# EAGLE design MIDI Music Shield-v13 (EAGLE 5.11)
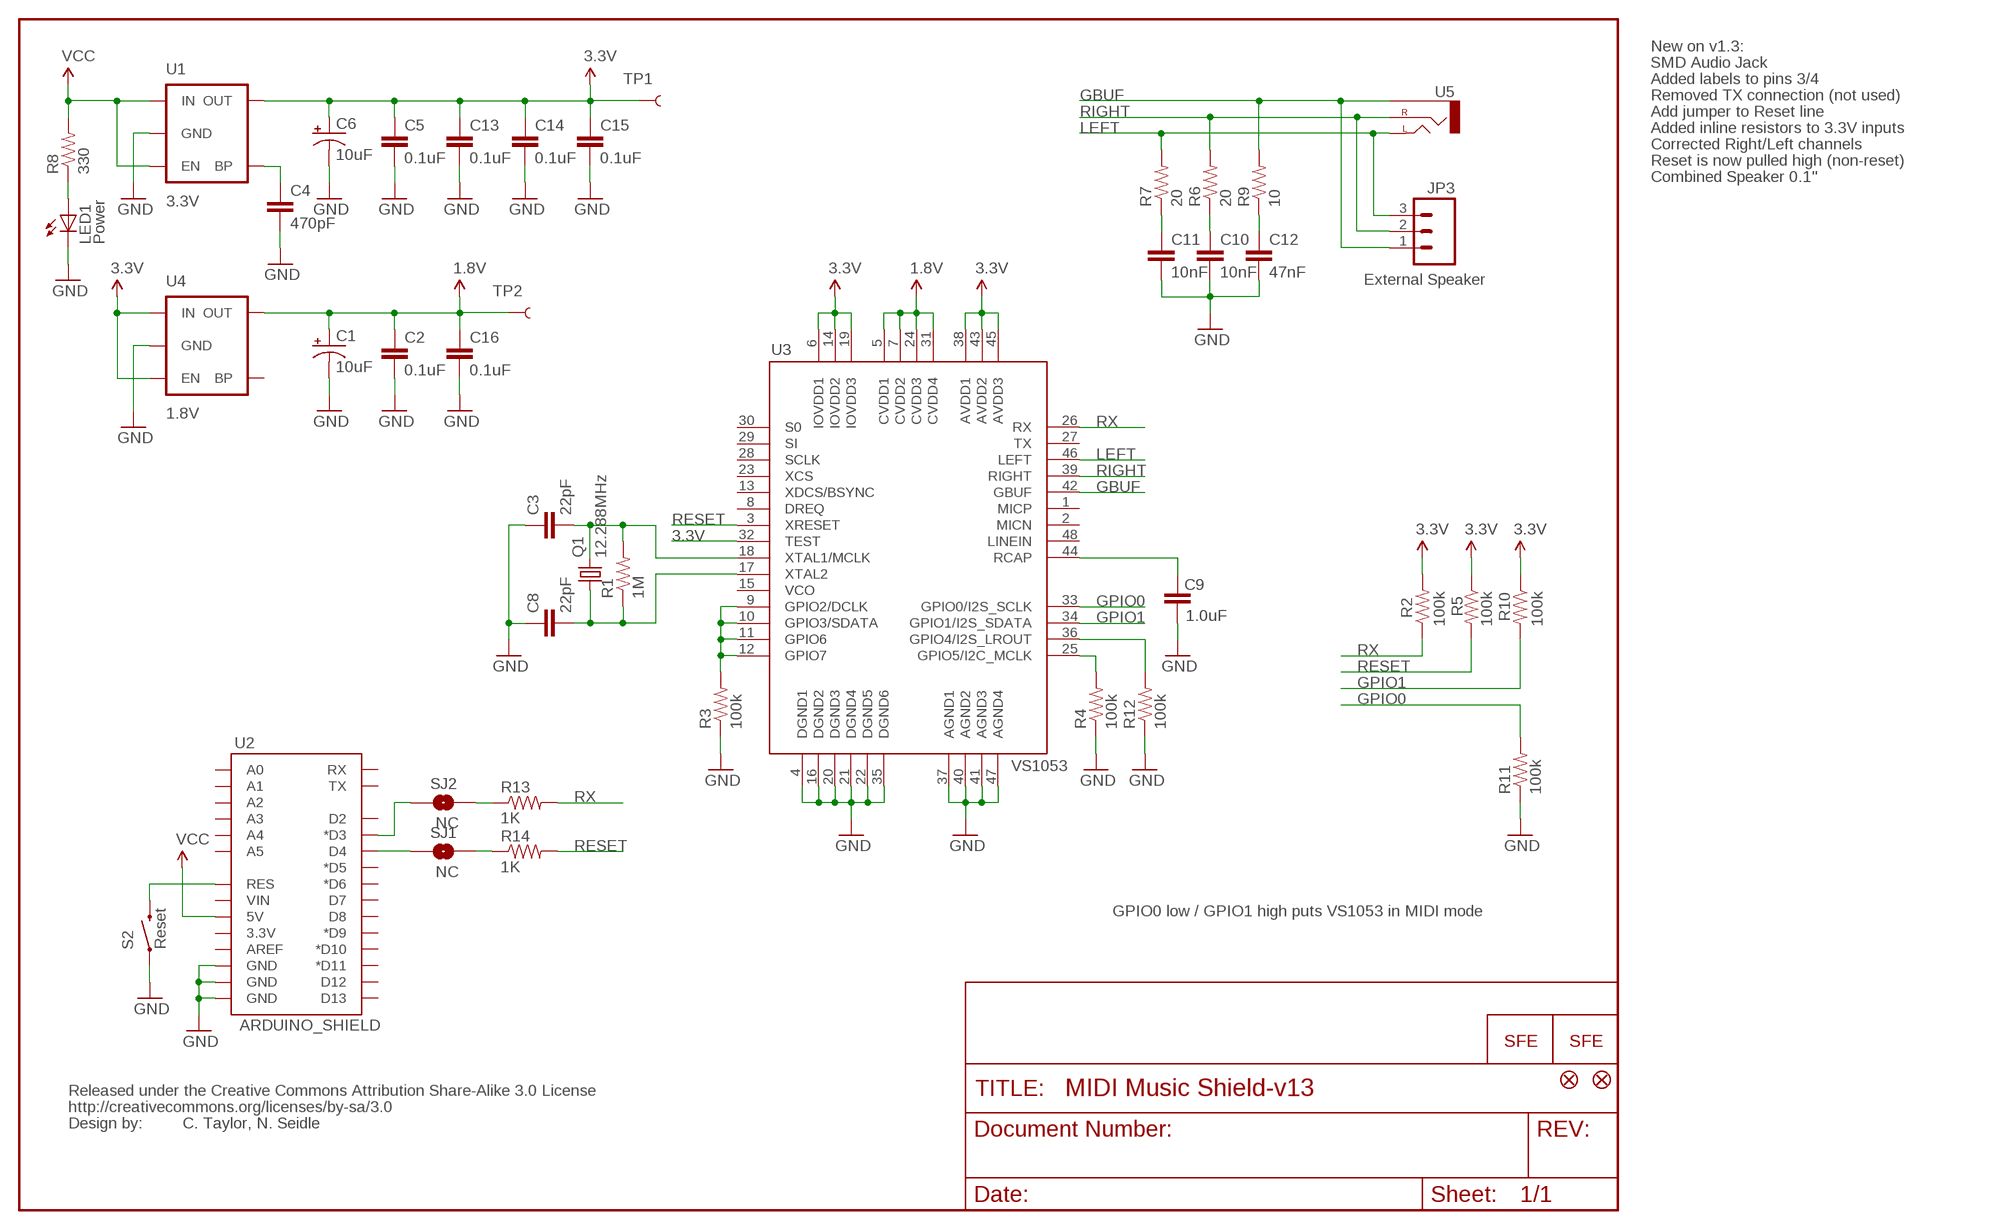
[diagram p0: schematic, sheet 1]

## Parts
C1  10uF  CAP_POL1206  [EIA3216]
C2  0.1uF  CAP0402-CAP  [0402-CAP]
C3  22pF  CAP0402-CAP  [0402-CAP]
C4  470pF  CAP0402-CAP  [0402-CAP]
C5  0.1uF  CAP0402-CAP  [0402-CAP]
C6  10uF  CAP_POL1206  [EIA3216]
C8  22pF  CAP0402-CAP  [0402-CAP]
C9  1.0uF  CAP0402-CAP  [0402-CAP]
C10  10nF  CAP0402-CAP  [0402-CAP]
C11  10nF  CAP0402-CAP  [0402-CAP]
C12  47nF  CAP0402-CAP  [0402-CAP]
C13  0.1uF  CAP0402-CAP  [0402-CAP]
C14  0.1uF  CAP0402-CAP  [0402-CAP]
C15  0.1uF  CAP0402-CAP  [0402-CAP]
C16  0.1uF  CAP0402-CAP  [0402-CAP]
JP3  External Speaker  M03PTH  [1X03]
LED1  Power  LED0603  [LED-0603]
Q1  12.288MHz  CRYSTAL5X3  [CRYSTAL-SMD-5X3]
R1  1M  RESISTOR0402-RES  [0402-RES]
R2  100k  RESISTOR0402-RES  [0402-RES]
R3  100k  RESISTOR0402-RES  [0402-RES]
R4  100k  RESISTOR0402-RES  [0402-RES]
R5  100k  RESISTOR0402-RES  [0402-RES]
R6  20  RESISTOR0402-RES  [0402-RES]
R7  20  RESISTOR0402-RES  [0402-RES]
R8  330  RESISTOR0402-RES  [0402-RES]
R9  10  RESISTOR0402-RES  [0402-RES]
R10  100k  RESISTOR0402-RES  [0402-RES]
R11  100k  RESISTOR0402-RES  [0402-RES]
R12  100k  RESISTOR0402-RES  [0402-RES]
R13  1K  RESISTOR0402-RES  [0402-RES]
R14  1K  RESISTOR0402-RES  [0402-RES]
S2  Reset  SWITCH-MOMENTARY-2SMD  [TACTILE_SWITCH_SMD]
SJ1  NC  SOLDERJUMPERTRACE  [SJ_2S-TRACE]
SJ2  NC  SOLDERJUMPERTRACE  [SJ_2S-TRACE]
TP1  TEST-POINT3X5  [PAD.03X.05]
TP2  TEST-POINT3X5  [PAD.03X.05]
U1  3.3V  V_REG_LDOSMD  [SOT23-5]
U2  ARDUINO_SHIELD  ARDUINO_SHIELDLABEL  [DUEMILANOVE_SHIELD]
U3  VS1053  VS1033  [LQFP-48]
U4  1.8V  V_REG_LDOSMD2  [SC70]
U5  AUDIO-JACKSMD2  [AUDIO-JACK-3.5MM-SMD]
U$3  CREATIVE_COMMONS  [CREATIVE_COMMONS]
U$4  FIDUCIAL1X2  [FIDUCIAL-1X2]
U$5  FIDUCIAL1X2  [FIDUCIAL-1X2]
U$7  LOGO-SFENEW  [SFE-NEW-WEBLOGO]
U$8  LOGO-SFENEW  [SFE-NEW-WEBLOGO]

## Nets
1.8V: C1.A(+) C2.1 C16.1 TP2.P$1 U3.5(CVDD1) U3.7(CVDD2) U3.24(CVDD3) U3.31(CVDD4) U4.5(OUT)
3.3V: C5.1 C6.A(+) C13.1 C14.1 C15.1 R2.2 R5.1 R10.1 TP1.P$1 U1.5(OUT) U3.6(IOVDD1) U3.14(IOVDD2) U3.19(IOVDD3) U3.32(TEST) U3.38(AVDD1) U3.43(AVDD2) U3.45(AVDD3) U4.1(IN) U4.3(EN)
ARST: S2.3 U2.RES
G1: R3.2 U3.9(GPIO2/DCLK) U3.10(GPIO3/SDATA) U3.11(GPIO6) U3.12(GPIO7)
G2: R4.2 U3.25(GPIO5/I2C_MCLK)
GBUF: JP3.1 R9.2 U3.42(GBUF) U5.SLEEVE
GND: C1.C(-) C2.2 C3.1 C4.2 C5.2 C6.C(-) C8.1 C9.1 C10.2 C11.2 C12.2 C13.2 C14.2 C15.2 C16.2 LED1.C R3.1 R4.1 R11.1 R12.1 S2.1 U1.2(GND) U2.GND@0(GND) U2.GND@1(GND) U2.GND@2(GND) U3.4(DGND1) U3.16(DGND2) U3.20(DGND3) U3.21(DGND4) U3.22(DGND5) U3.35(DGND6) U3.37(AGND1) U3.40(AGND2) U3.41(AGND3) U3.47(AGND4) U4.2(GND)
GPIO0: R11.2 U3.33(GPIO0/I2S_SCLK)
GPIO1: R10.2 U3.34(GPIO1/I2S_SDATA)
LEFT: JP3.3 R7.2 U3.46(LEFT) U5.TIP(LEFT)
N$1: C9.2 U3.44(RCAP)
N$2: C12.1 R9.1
N$3: C10.1 R6.1
N$5: C11.1 R7.1
N$6: LED1.A R8.1
N$7: SJ1.1 U2.D4
N$8: R13.1 SJ2.2
N$9: C3.2 Q1.3 R1.2 U3.18(XTAL1/MCLK)
N$10: C8.2 Q1.1 R1.1 U3.17(XTAL2)
N$11: R14.1 SJ1.2
N$13: SJ2.1 U2.D3(*D3)
N$70: C4.1 U1.4(BP)
N$73: R12.2 U3.36(GPIO4/I2S_LROUT)
RESET: R5.2 R14.2 U3.3(XRESET)
RIGHT: JP3.2 R6.2 U3.39(RIGHT) U5.RING(RIGHT)
RX: R2.1 R13.2 U3.26(RX)
VCC: R8.2 U1.1(IN) U1.3(EN) U2.5V
Unconnected: U2.3.3V U2.A0 U2.A1 U2.A2 U2.A3 U2.A4 U2.A5 U2.AREF U2.D2 U2.D5(*D5) U2.D6(*D6) U2.D7 U2.D8 U2.D9(*D9) U2.D10(*D10) U2.D11(*D11) U2.D12 U2.D13 U2.RX U2.TX U2.VIN U3.1(MICP) U3.2(MICN) U3.8(DREQ) U3.13(XDCS/BSYNC) U3.15(VCO) U3.23(XCS) U3.27(TX) U3.28(SCLK) U3.29(SI) U3.30(S0) U3.48(LINEIN) U4.4(BP)

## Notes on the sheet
- New on v1.3:
- SMD Audio Jack
- Added labels to pins 3/4
- Removed TX connection (not used)
- Add jumper to Reset line
- Added inline resistors to 3.3V inputs
- Corrected Right/Left channels
- Reset is now pulled high (non-reset)
- Combined Speaker 0.1"
- GPIO0 low / GPIO1 high puts VS1053 in MIDI mode
- C. Taylor, N. Seidle

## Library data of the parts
C1 C6 = SparkFun:CAP_POL: Capacitor Polarized
C2-C5 C8-C16 = SparkFun:CAP: Capacitor
JP3 = SparkFun:M03: Header 3 Standard 3-pin 0.1" header. Use with straight break away headers (SKU : PRT-00116), right angle break away headers (PRT-00553), swiss pins (PRT-00743), machine pins (PRT-00117), and female headers (PRT-00115). Molex polarized connector foot print use with SKU : PRT-08232 with associated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
LED1 = SparkFun:LED: LEDs
Q1 = SparkFun:CRYSTAL: Crystals
R1-R14 = SparkFun:RESISTOR: Resistor
S2 = SparkFun:SWITCH-MOMENTARY-2
SJ1 SJ2 = SparkFun:SOLDERJUMPER: Solder Jumper
TP1 TP2 = SparkFun:TEST-POINT
U1 U4 = SparkFun:V_REG_LDO: Voltage Regulator LDO Standard 150mA LDO voltage regulator in SOT-23 layout. Micrel part MIC5205. BP (by-pass) pin is used to lower output noise with 470pF cap.
U2 = SparkFun:ARDUINO_SHIELD
U3 = SparkFun:VS1033
U5 = SparkFun:AUDIO-JACK: 3.5mm Audio Jack Simple 3.5mm common PCB mount audio jack. SKU: PRT-08032
U$3 = SparkFun:CREATIVE_COMMONS
U$4 U$5 = SparkFun:FIDUCIAL: Fiducial Alignment Points
U$7 U$8 = SparkFun:LOGO-SFE: Spark Fun Electronics PCB Logo

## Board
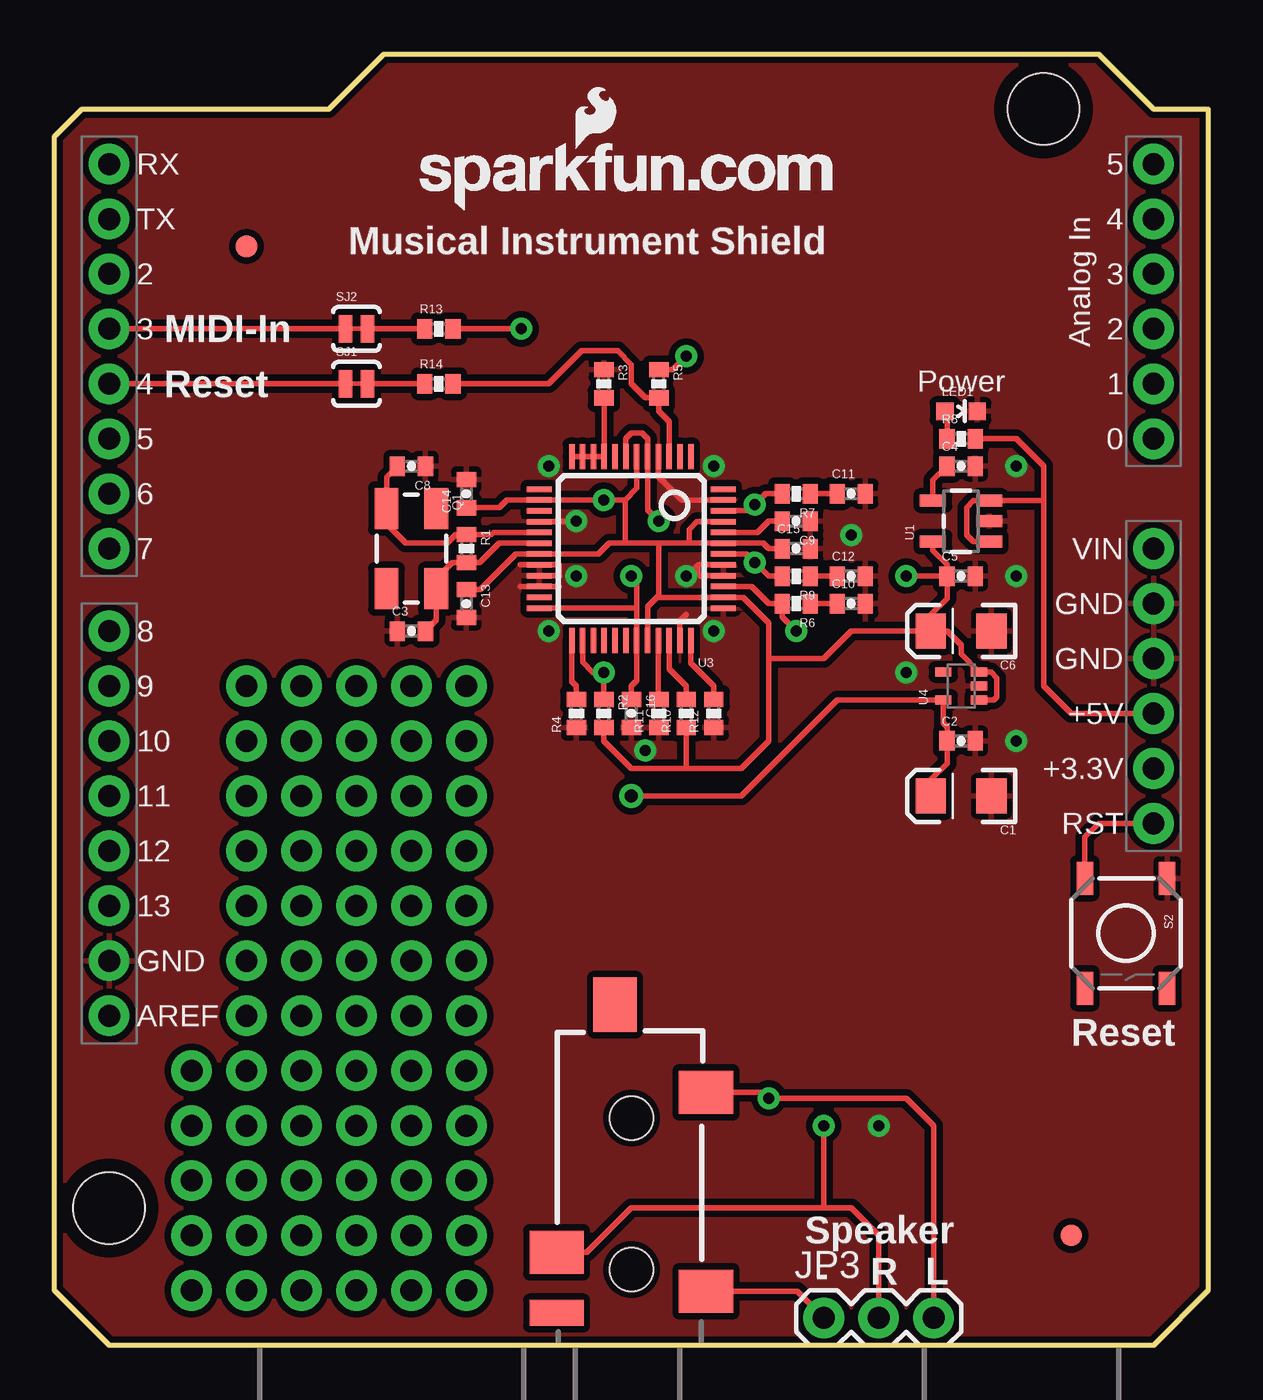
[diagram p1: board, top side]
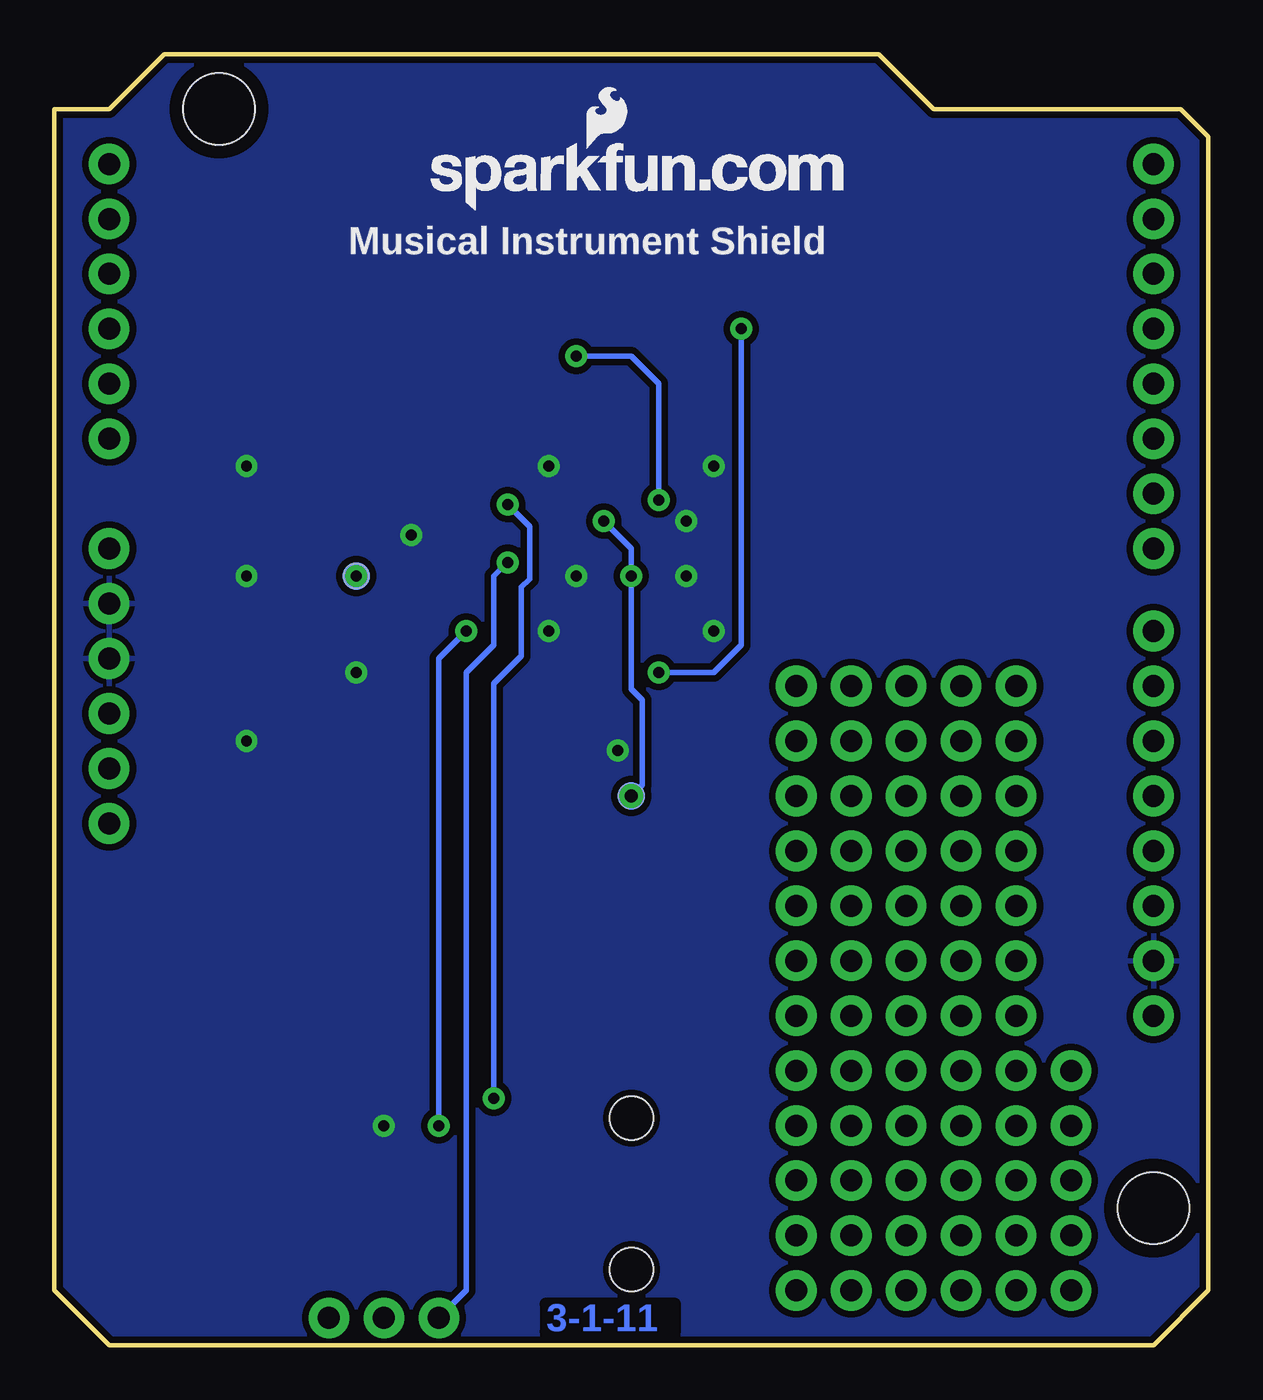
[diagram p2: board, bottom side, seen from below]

Size 53.34 x 59.69 mm. Coordinates in mm from the lower left corner, seen from the top.
Outline: 0,55.88 1.27,57.15 12.7,57.15 15.24,59.69 48.26,59.69 50.8,57.15 53.34,57.15 53.34,2.54 50.8,0 2.54,0 0,2.54 0,55.88
Copper layers (1*16): Top 0.035mm / dielectric 1.5mm / Bottom 0.035mm
Design rules "SparkFun *": minimum track width 8mil, minimum drill 20mil, track to track 8mil, track to pad 8mil, pad to pad 8mil, via to via 8mil, smd to smd 8mil, copper to edge 9mil, drill to drill 7mil, minimum pad ring 12mil, minimum via ring 10mil, stop-mask expansion 4mil, vias tented up to drill 20mil, thermal gap 10mil

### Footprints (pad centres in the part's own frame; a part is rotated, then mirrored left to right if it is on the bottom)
EIA3216 = smd 1.4 x 1.6: A 1.4,0; C -1.4,0
0402-CAP = smd 0.7 x 0.9: 1 -0.65,0; 2 0.65,0
1X03 = drill 1.016 pad 1.88 round: 1 0,0; 2 2.54,0; 3 5.08,0
LED-0603 = smd 0.8 x 0.8: A 0,-0.75; C 0,0.75
CRYSTAL-SMD-5X3 = smd 1.9 x 1.1: 1 -1.85,-1.15; 2 1.85,-1.15; 3 1.85,1.15; 4 -1.85,1.15
0402-RES = smd 0.7 x 0.9: 1 -0.65,0; 2 0.65,0
TACTILE_SWITCH_SMD = smd 1.524 x 0.762: 1 -2.54,1.905; 2 2.54,1.905; 3 -2.54,-1.905; 4 2.54,-1.905
SJ_2S-TRACE = smd 0.635 x 1.27: 1 -0.508,0; 2 0.508,0
PAD.03X.05 = smd 1.27 x 1.27: P$1 0,0
SOT23-5 = smd 0.55 x 1.2: 1 -0.95,-1.3; 2 0,-1.3; 3 0.95,-1.3; 4 0.95,1.3; 5 -0.95,1.3
DUEMILANOVE_SHIELD = drill 1.016 pad 1.88 round: 3.3V 50.8,26.67; 5V 50.8,29.21; A0 50.8,41.91; A1 50.8,44.45; A2 50.8,46.99; A3 50.8,49.53; A4 50.8,52.07; A5 50.8,54.61; AREF 2.54,15.24; D2 2.54,49.53; D3 2.54,46.99; D4 2.54,44.45; D5 2.54,41.91; D6 2.54,39.37; D7 2.54,36.83; D8 2.54,33.02; D9 2.54,30.48; D10 2.54,27.94; D11 2.54,25.4; D12 2.54,22.86; D13 2.54,20.32; GND@0 50.8,31.75; GND@1 50.8,34.29; GND@2 2.54,17.78; RES 50.8,24.13; RX 2.54,54.61; TX 2.54,52.07; VIN 50.8,36.83 | hole 3.302: 45.72,57.15; 2.54,6.35
LQFP-48 = smd 0.254 x 1.143: 1 -2.75,-4.25; 2 -2.25,-4.25; 3 -1.75,-4.25; 4 -1.25,-4.25; 5 -0.75,-4.25; 6 -0.25,-4.25; 7 0.25,-4.25; 8 0.75,-4.25; 9 1.25,-4.25; 10 1.75,-4.25; 11 2.25,-4.25; 12 2.75,-4.25; 25 2.75,4.25; 26 2.25,4.25; 27 1.75,4.25; 28 1.25,4.25; 29 0.75,4.25; 30 0.25,4.25; 31 -0.25,4.25; 32 -0.75,4.25; 33 -1.25,4.25; 34 -1.75,4.25; 35 -2.25,4.25; 36 -2.75,4.25 | smd 1.143 x 0.254: 13 4.25,-2.75; 14 4.25,-2.25; 15 4.25,-1.75; 16 4.25,-1.25; 17 4.25,-0.75; 18 4.25,-0.25; 19 4.25,0.25; 20 4.25,0.75; 21 4.25,1.25; 22 4.25,1.75; 23 4.25,2.25; 24 4.25,2.75; 37 -4.25,2.75; 38 -4.25,2.25; 39 -4.25,1.75; 40 -4.25,1.25; 41 -4.25,0.75; 42 -4.25,0.25; 43 -4.25,-0.25; 44 -4.25,-0.75; 45 -4.25,-1.25; 46 -4.25,-1.75; 47 -4.25,-2.25; 48 -4.25,-2.75
SC70 = smd 0.4 x 0.75: 1 -0.65,-0.825; 2 0,-0.825; 3 0.65,-0.825; 4 0.65,0.825; 5 -0.65,0.825
AUDIO-JACK-3.5MM-SMD = smd 2 x 2.5: RING 4.3,3.45; SLEEVE 2.5,-3.45; TIP 11.7,-3.45 | smd 1.2 x 2.5: RSH 1.5,3.45 | smd 2.5 x 2: TSH 15.75,0.75 | hole 2: 3.5,0; 10.5,0
FIDUCIAL-1X2 = smd 1 x 1: 1 0,0

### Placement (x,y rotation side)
C1  41.91,25.4 180 top
C2  41.91,27.94 0 top
C3  16.51,33.02 0 top
C4  41.91,40.64 0 top
C5  41.91,35.56 0 top
C6  41.91,33.02 180 top
C8  16.51,40.64 180 top
C9  34.29,38.1 180 top
C10  36.83,34.29 0 top
C11  36.83,39.37 0 top
C12  36.83,35.56 0 top
C13  19.05,34.29 270 top
C14  19.05,39.37 90 top
C15  34.29,36.83 0 top
C16  26.67,29.21 270 top
JP3  35.56,1.27 0 top
LED1  41.91,43.18 270 top
Q1  16.51,36.83 270 top
R1  19.05,36.83 270 top
R2  25.4,29.21 270 top
R3  25.4,44.45 270 top
R4  24.13,29.21 90 top
R5  27.94,44.45 270 top
R6  34.29,34.29 180 top
R7  34.29,39.37 180 top
R8  41.91,41.91 0 top
R9  34.29,35.56 180 top
R10  29.21,29.21 90 top
R11  27.94,29.21 90 top
R12  30.48,29.21 90 top
R13  17.78,46.99 0 top
R14  17.78,44.45 0 top
S2  49.53,19.05 270 top
SJ1  13.97,44.45 0 top
SJ2  13.97,46.99 0 top
TP1  39.37,35.56 0 bottom
TP2  26.67,25.4 0 bottom
U1  41.91,38.1 90 top
U2  0,0 0 top
U3  26.67,36.83 180 top
U4  41.91,30.48 90 top
U5  26.67,0 90 top
U$3  not placed on the board
U$4  46.99,5.08 0 top
U$5  8.89,50.8 0 top
U$7  16.89,52.45 0 top
U$8  35.94,52.45 0 bottom

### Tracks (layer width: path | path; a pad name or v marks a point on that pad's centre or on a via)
1.8V  (via drill 0.51, 0.6)
  Top 0.254: C1.A 40.51,26.16 41.26,26.91 C2.1 41.26,28.59 41.09,28.77 U4.5 36.18,29.83 31.75,25.4 TP2.P$1 | 26.92,34.04 U3.31 26.92,30.73 26.67,30.48 C16.1 | 26.92,34.04 26.92,35.31 v26.67,35.56 | U3.24 26.88,34.08 26.92,34.04 | v27.94,38.1 27.42,38.62 U3.5 27.42,41.92 27.18,42.16 26.67,42.16 26.42,41.91 U3.7
  Bottom 0.254: v27.94,38.1 26.67,36.83 v26.67,35.56 26.67,30.35 26.16,29.84 26.16,25.91 TP2.P$1
  other vias: 26.67,25.4
3.3V  (via drill 0.51)
  Top 0.254: C5.1 41.26,34.53 40.51,33.78 C6.A | C5.1 41.26,36.08 40.61,36.73 U1.5 40.61,36.8 | 26.42,37.08 25.65,37.08 25.15,36.58 U3.19 21.34,36.58 19.7,34.94 C13.1 | 26.42,37.08 27.94,37.08 | 27.94,37.08 29.34,37.08 | 29.34,37.08 U3.43 32.77,37.08 33.02,36.83 C15.1 | U3.45 29.7,38.08 29.34,37.72 29.34,37.08 | 26.42,37.08 26.38,37.12 26.38,39.08 | C14.1 20.56,38.72 20.92,39.08 U3.14 v25.4,39.08 26.38,39.08 | 27.85,34.58 U3.38 31.84,34.58 33.02,33.4 33.02,31.75 | U3.32 27.42,34.15 27.85,34.58 | 27.94,37.08 27.94,34.67 27.85,34.58 | 29.21,26.67 R10.1 | R2.2 25.4,27.94 26.67,26.67 29.21,26.67 | U3.6 26.92,39.62 26.38,39.08 | C6.A 36.83,33.02 35.56,31.75 33.02,31.75 | 29.21,26.67 31.75,26.67 33.02,27.94 33.02,31.75 | U4.1 43.42,29.83 43.56,29.97 43.56,30.86 43.29,31.13 U4.3 41.91,31.95 41.91,32.38 41.27,33.02 C6.A | C5.1 TP1.P$1 | R5.1 28.59,45.1 v29.21,45.72
  Bottom 0.254: v29.21,45.72 26.67,45.72 25.4,44.45 v25.4,39.08
  other vias: 39.37,35.56
ARST
  Top 0.254: S2.3 47.62,23.5 48.26,24.13 U2.RES
G1
  Top 0.254: U3.12 U3.11 U3.10 U3.9 25.42,43.78 R3.2
G2
  Top 0.254: U3.25 23.92,30.69 24.13,30.48 R4.2
GBUF  (via drill 0.51)
  Top 0.254: R9.2 33.02,35.56 v32.38,36.2 32,36.58 U3.42 | U5.SLEEVE 34.33,2.5 JP3.1
  Bottom 0.254: v32.38,36.2 33.02,35.56 33.02,32.38 34.29,31.11 34.29,2.54 JP3.1
GND  (via drill 0.51)
  Top 0.254: U3.4 27.92,40.15 28.99,39.08 U3.47 | v29.21,35.56 29.73,36.08 29.73,35.67 29.84,35.56 29.86,35.58 U3.40 | U3.35 28.92,33.49 29.21,33.78 | U3.16 24.11,38.08 v24.13,38.1 | v24.13,35.56 24.11,35.58 | 29.86,36.09 U3.41 | U3.21 23.35,35.58 | 23.35,35.58 23.37,35.56 | 21.53,36.09 23.35,36.09 23.35,35.58 | 21.53,35.07 23.35,35.07
  other vias: 30.48,33.02 39.37,31.11 27.3,27.51 30.48,40.64 36.83,37.47 22.86,40.64 44.45,35.56 44.45,27.94 44.45,40.64 38.1,10.16 22.86,33.02
  pour Top (isolate 0.305): 0,59.69 53.34,59.69 53.34,0 0,0
  pour Bottom (isolate 0.305): 0,0 0,59.69 53.34,59.69 53.34,0
GPIO0
  Top 0.254: U3.33 27.92,29.88 R11.2
GPIO1
  Top 0.254: U3.34 28.42,31.27 29.21,30.48 R10.2
LEFT  (via drill 0.51)
  Top 0.254: U3.46 32.1,38.58 v32.38,38.86 32.89,39.37 R7.2 | U5.TIP 32.75,11.7 v33.02,11.43 39.37,11.43 40.64,10.16 JP3.3
  Bottom 0.254: v32.38,38.86 31.37,37.85 31.37,35.43 31.75,35.05 31.75,31.88 33.02,30.61 v33.02,11.43
N$1
  Top 0.254: U3.44 32.5,37.58 33.02,38.1 C9.2
N$2
  Top 0.254: R9.1 C12.1
N$3
  Top 0.254: R6.1 C10.1
N$4  (via drill 1.02 pad 1.88)
  other vias: 19.05,22.86
N$5
  Top 0.254: R7.1 C11.1
N$6
  Top 0.254: R8.1 41.26,43.08 LED1.A
N$7
  Top 0.254: U2.D4 SJ1.1
N$8
  Top 0.254: SJ2.2 R13.1
N$9
  Top 0.254: U3.18 20.57,37.08 19.67,36.18 R1.2 18.4,36.18 17.78,35.56 17.78,35.1 Q1.3 17.66,33.52 C3.2
N$10
  Top 0.254: U3.17 20.31,37.58 20.21,37.48 R1.1 18.56,37.48 18.16,37.08 16.26,37.08 15.24,38.1 15.24,38.56 Q1.1 15.36,40.14 C8.2
N$11
  Top 0.254: SJ1.2 R14.1
N$13
  Top 0.254: U2.D3 SJ2.1
N$16  (via drill 1.02 pad 1.88)
  other vias: 8.89,20.32
N$17  (via drill 1.02 pad 1.88)
  other vias: 11.43,20.32
N$18  (via drill 1.02 pad 1.88)
  other vias: 13.97,20.32
N$19  (via drill 1.02 pad 1.88)
  other vias: 16.51,20.32
N$20  (via drill 1.02 pad 1.88)
  other vias: 19.05,20.32
N$28  (via drill 1.02 pad 1.88)
  other vias: 8.89,17.78
N$29  (via drill 1.02 pad 1.88)
  other vias: 11.43,17.78
N$30  (via drill 1.02 pad 1.88)
  other vias: 13.97,17.78
N$31  (via drill 1.02 pad 1.88)
  other vias: 16.51,17.78
N$32  (via drill 1.02 pad 1.88)
  other vias: 19.05,17.78
N$40  (via drill 1.02 pad 1.88)
  other vias: 8.89,15.24
N$41  (via drill 1.02 pad 1.88)
  other vias: 11.43,15.24
N$42  (via drill 1.02 pad 1.88)
  other vias: 13.97,15.24
N$43  (via drill 1.02 pad 1.88)
  other vias: 16.51,15.24
N$44  (via drill 1.02 pad 1.88)
  other vias: 19.05,15.24
N$52  (via drill 1.02 pad 1.88)
  other vias: 8.89,12.7
N$53  (via drill 1.02 pad 1.88)
  other vias: 11.43,12.7
N$54  (via drill 1.02 pad 1.88)
  other vias: 13.97,12.7
N$55  (via drill 1.02 pad 1.88)
  other vias: 16.51,12.7
N$56  (via drill 1.02 pad 1.88)
  other vias: 19.05,12.7
N$64  (via drill 1.02 pad 1.88)
  other vias: 8.89,10.16
N$65  (via drill 1.02 pad 1.88)
  other vias: 11.43,10.16
N$66  (via drill 1.02 pad 1.88)
  other vias: 13.97,10.16
N$67  (via drill 1.02 pad 1.88)
  other vias: 16.51,10.16
N$68  (via drill 1.02 pad 1.88)
  other vias: 19.05,10.16
N$70
  Top 0.254: U1.4 40.61,39.99 C4.1
N$73
  Top 0.254: U3.36 29.42,31.54 30.48,30.48 R12.2
N$76  (via drill 1.02 pad 1.88)
  other vias: 8.89,7.62
N$77  (via drill 1.02 pad 1.88)
  other vias: 11.43,7.62
N$78  (via drill 1.02 pad 1.88)
  other vias: 13.97,7.62
N$79  (via drill 1.02 pad 1.88)
  other vias: 16.51,7.62
N$80  (via drill 1.02 pad 1.88)
  other vias: 19.05,7.62
N$88  (via drill 1.02 pad 1.88)
  other vias: 8.89,5.08
N$89  (via drill 1.02 pad 1.88)
  other vias: 11.43,5.08
N$90  (via drill 1.02 pad 1.88)
  other vias: 13.97,5.08
N$91  (via drill 1.02 pad 1.88)
  other vias: 16.51,5.08
N$92  (via drill 1.02 pad 1.88)
  other vias: 19.05,5.08
N$95  (via drill 1.02 pad 1.88)
  other vias: 19.05,25.4
N$96  (via drill 1.02 pad 1.88)
  other vias: 16.51,25.4
N$97  (via drill 1.02 pad 1.88)
  other vias: 13.97,25.4
N$99  (via drill 1.02 pad 1.88)
  other vias: 8.89,25.4
N$100  (via drill 1.02 pad 1.88)
  other vias: 8.89,2.54
N$101  (via drill 1.02 pad 1.88)
  other vias: 11.43,2.54
N$102  (via drill 1.02 pad 1.88)
  other vias: 13.97,2.54
N$103  (via drill 1.02 pad 1.88)
  other vias: 16.51,2.54
N$104  (via drill 1.02 pad 1.88)
  other vias: 19.05,2.54
N$105  (via drill 1.02 pad 1.88)
  other vias: 8.89,27.94
N$106  (via drill 1.02 pad 1.88)
  other vias: 11.43,25.4
N$107  (via drill 1.02 pad 1.88)
  other vias: 11.43,27.94
N$110  (via drill 1.02 pad 1.88)
  other vias: 13.97,27.94
N$111  (via drill 1.02 pad 1.88)
  other vias: 16.51,27.94
N$112  (via drill 1.02 pad 1.88)
  other vias: 6.35,12.7
N$113  (via drill 1.02 pad 1.88)
  other vias: 6.35,10.16
N$114  (via drill 1.02 pad 1.88)
  other vias: 6.35,7.62
N$115  (via drill 1.02 pad 1.88)
  other vias: 6.35,5.08
N$116  (via drill 1.02 pad 1.88)
  other vias: 6.35,2.54
N$122  (via drill 1.02 pad 1.88)
  other vias: 19.05,27.94
N$123  (via drill 1.02 pad 1.88)
  other vias: 19.05,30.48
N$124  (via drill 1.02 pad 1.88)
  other vias: 16.51,30.48
N$125  (via drill 1.02 pad 1.88)
  other vias: 13.97,30.48
N$126  (via drill 1.02 pad 1.88)
  other vias: 11.43,30.48
N$127  (via drill 1.02 pad 1.88)
  other vias: 8.89,30.48
N$130  (via drill 1.02 pad 1.88)
  other vias: 8.89,22.86
N$131  (via drill 1.02 pad 1.88)
  other vias: 11.43,22.86
N$132  (via drill 1.02 pad 1.88)
  other vias: 13.97,22.86
N$133  (via drill 1.02 pad 1.88)
  other vias: 16.51,22.86
RESET
  Top 0.254: U3.3 28.42,42.7 27.94,43.18 R5.2 27.32,43.8 26.67,44.45 26.67,45.34 26.04,45.97 24.38,45.97 22.86,44.45 R14.2
RIGHT  (via drill 0.51)
  Top 0.254: U3.39 32.23,35.08 33.02,34.29 R6.2 33.64,33.67 v34.29,33.02 | U5.RING 24.62,4.3 26.67,6.35 35.56,6.35 | 35.56,6.35 v35.56,10.16 | 35.56,6.35 36.83,6.35 38.1,5.08 JP3.2
  Bottom 0.254: v34.29,33.02 35.56,31.75 v35.56,10.16
RX  (via drill 0.51)
  Top 0.254: R2.1 v25.4,31.11 24.89,31.11 24.42,31.59 U3.26 | v21.59,46.99 R13.2
  Bottom 0.254: v25.4,31.11 22.86,31.11 21.59,32.38 v21.59,46.99
VCC
  Top 0.254: U1.1 42.48,37.15 42.16,37.47 42.16,38.73 42.48,39.05 U1.3 45.65,39.05 45.72,39.12 | U2.5V 46.99,29.21 45.72,30.48 45.72,39.12 | R8.2 44.45,41.91 45.72,40.64 45.72,39.12

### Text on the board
Bottom: 3-1-11
tPlace: Musical Instrument Shield | MIDI-In | Reset | Power | Reset | Speaker | - | R | L | C. Taylor, N. Seidle
bPlace: Musical Instrument Shield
